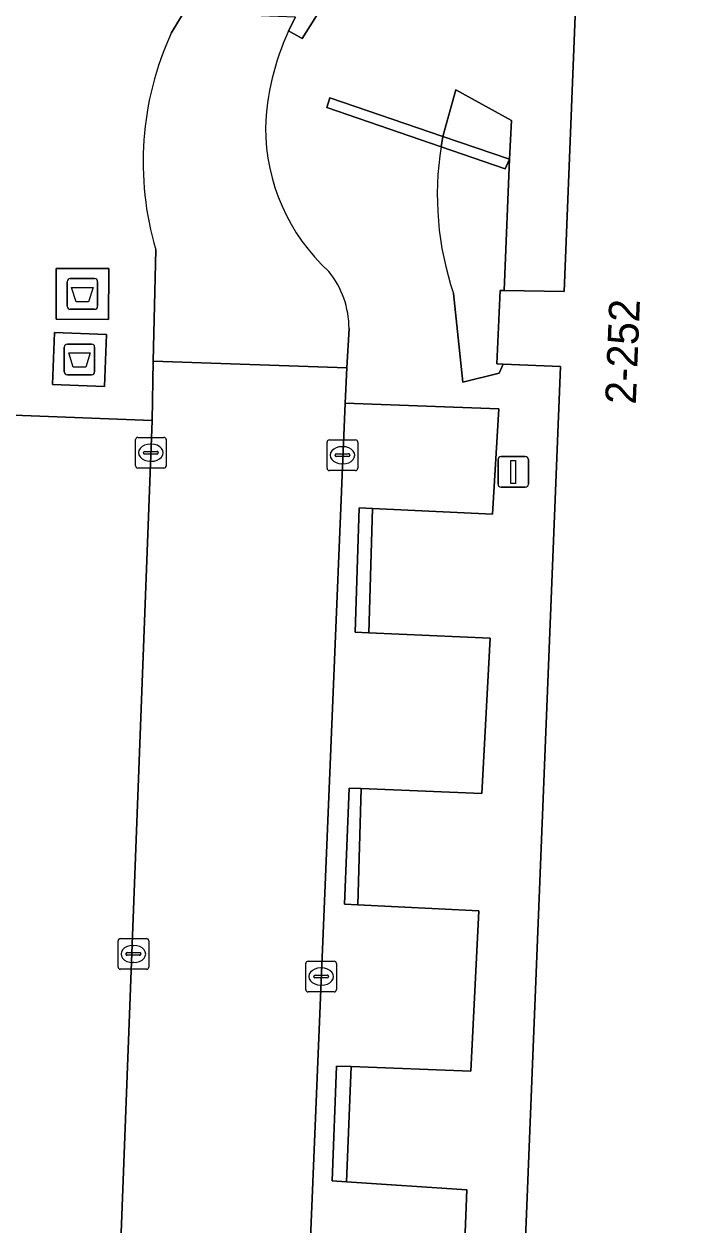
# Model space of a CAD drawing. Extents: x 160077 to 160948, y 386481 to 387498.
# Drawn here: x 160852.52 to 160874.27, y 386651.4 to 386690.54 of the extents above; entities that cross this region are included whole.
import ezdxf

# ---------------------------------------------------------------- set-up
doc = ezdxf.new("R2010")
doc.units = 0
for name, color, linetype in [('IMGEO_Afval_apart_plaats', 7, 'Continuous'), ('IMGEO_Kolk', 7, 'Continuous'), ('IMGEO_Lichtmast', 7, 'Continuous'), ('IMGEO_Muur', 7, 'Continuous'), ('IMGEO_Pand', 7, 'Continuous'), ('IMGEO_Pand_nummerreeks', 7, 'Continuous'), ('IMGEO_Parkeervlak_open', 7, 'Continuous'), ('IMGEO_Rijbaan_lokaal_open', 7, 'Continuous'), ('IMGEO_Voetpad_gesloten', 7, 'Continuous'), ('IMGEO_Voetpad_open', 7, 'Continuous')]:
    doc.layers.add(name, color=color, linetype=linetype)

msp = doc.modelspace()

# ---------------------------------------------------------------- linework, layer by layer
at = {"layer": 'IMGEO_Afval_apart_plaats'}
for p, q in [((160853.93, 386681.341), (160853.93, 386682.141)), ((160853.93, 386682.141), (160853.93, 386681.341)), ((160854.03, 386682.241), (160854.82, 386682.241)), ((160854.82, 386682.241), (160854.03, 386682.241)), ((160854.92, 386682.141), (160854.92, 386681.341)), ((160854.92, 386681.341), (160854.92, 386682.141)), ((160854.82, 386681.241), (160854.03, 386681.241)), ((160854.03, 386681.241), (160854.82, 386681.241)), ((160853.933, 386680.106), (160854.723, 386680.106)), ((160854.723, 386680.106), (160853.933, 386680.106)), ((160853.833, 386679.206), (160853.833, 386680.006)), ((160853.833, 386680.006), (160853.833, 386679.206)), ((160854.823, 386680.006), (160854.823, 386679.206)), ((160854.823, 386679.206), (160854.823, 386680.006)), ((160854.723, 386679.106), (160853.933, 386679.106)), ((160853.933, 386679.106), (160854.723, 386679.106))]:
    msp.add_line(p, q, dxfattribs=at)
for points in [[(160854.073, 386681.955), (160854.777, 386681.955), (160854.628, 386681.485), (160854.222, 386681.485), (160854.073, 386681.955)], [(160853.976, 386679.82), (160854.68, 386679.82), (160854.531, 386679.35), (160854.125, 386679.35), (160853.976, 386679.82)]]:
    msp.add_lwpolyline(points, dxfattribs=at)
for centre, start, end in [((160854.03, 386682.141), 90, 180), ((160854.03, 386682.141), 90, 180), ((160854.82, 386682.141), 0, 90), ((160854.82, 386682.141), 360, 90), ((160854.03, 386681.341), 180, 270), ((160854.03, 386681.341), 180, 270), ((160854.82, 386681.341), 270, 0), ((160854.82, 386681.341), 270, 0), ((160853.933, 386680.006), 90, 180), ((160853.933, 386680.006), 90, 180), ((160854.723, 386680.006), 0, 90), ((160854.723, 386680.006), 360, 90), ((160853.933, 386679.206), 180, 270), ((160853.933, 386679.206), 180, 270), ((160854.723, 386679.206), 270, 0), ((160854.723, 386679.206), 270, 0)]:
    msp.add_arc(centre, 0.1, start, end, dxfattribs=at)
at = {"layer": 'IMGEO_Kolk'}
for p, q in [((160856.155, 386676.141), (160856.155, 386676.993)), ((160856.23, 386677.067), (160857.082, 386677.067)), ((160857.156, 386676.993), (160857.156, 386676.141)), ((160862.477, 386676.984), (160863.329, 386676.984)), ((160856.414, 386676.561), (160856.414, 386676.573)), ((160856.457, 386676.61), (160856.855, 386676.61)), ((160856.643, 386676.847), (160856.668, 386676.847)), ((160856.898, 386676.573), (160856.898, 386676.561)), ((160862.402, 386676.058), (160862.402, 386676.91)), ((160862.89, 386676.764), (160862.915, 386676.764)), ((160863.403, 386676.91), (160863.403, 386676.058)), ((160856.852, 386676.524), (160856.454, 386676.524)), ((160856.666, 386676.287), (160856.641, 386676.287)), ((160862.661, 386676.478), (160862.661, 386676.49)), ((160863.099, 386676.441), (160862.701, 386676.441)), ((160862.704, 386676.527), (160863.102, 386676.527)), ((160862.913, 386676.204), (160862.888, 386676.204)), ((160863.145, 386676.49), (160863.145, 386676.478)), ((160857.082, 386676.067), (160856.23, 386676.067)), ((160863.329, 386675.984), (160862.477, 386675.984)), ((160855.585, 386659.803), (160855.585, 386660.655)), ((160855.66, 386660.729), (160856.512, 386660.729)), ((160856.073, 386660.509), (160856.098, 386660.509)), ((160856.586, 386660.655), (160856.586, 386659.803)), ((160855.844, 386660.223), (160855.844, 386660.235)), ((160856.282, 386660.186), (160855.884, 386660.186)), ((160855.887, 386660.272), (160856.285, 386660.272)), ((160856.328, 386660.235), (160856.328, 386660.223)), ((160856.512, 386659.729), (160855.66, 386659.729)), ((160856.096, 386659.949), (160856.071, 386659.949)), ((160861.707, 386659.067), (160861.707, 386659.919)), ((160861.782, 386659.993), (160862.634, 386659.993)), ((160862.195, 386659.773), (160862.22, 386659.773)), ((160862.708, 386659.919), (160862.708, 386659.067)), ((160861.966, 386659.487), (160861.966, 386659.499)), ((160862.404, 386659.45), (160862.006, 386659.45)), ((160862.009, 386659.536), (160862.407, 386659.536)), ((160862.45, 386659.499), (160862.45, 386659.487)), ((160862.634, 386658.993), (160861.782, 386658.993)), ((160862.218, 386659.213), (160862.193, 386659.213))]:
    msp.add_line(p, q, dxfattribs=at)
for points in [[(160856.155, 386676.141), (160856.155, 386676.993)], [(160856.23, 386677.067), (160857.082, 386677.067)], [(160857.156, 386676.993), (160857.156, 386676.141)], [(160862.477, 386676.984), (160863.329, 386676.984)], [(160862.402, 386676.058), (160862.402, 386676.91)], [(160863.403, 386676.91), (160863.403, 386676.058)], [(160857.082, 386676.067), (160856.23, 386676.067)], [(160863.329, 386675.984), (160862.477, 386675.984)], [(160855.585, 386659.803), (160855.585, 386660.655)], [(160855.66, 386660.729), (160856.512, 386660.729)], [(160856.586, 386660.655), (160856.586, 386659.803)], [(160856.512, 386659.729), (160855.66, 386659.729)], [(160861.707, 386659.067), (160861.707, 386659.919)], [(160861.782, 386659.993), (160862.634, 386659.993)], [(160862.708, 386659.919), (160862.708, 386659.067)], [(160862.634, 386658.993), (160861.782, 386658.993)]]:
    msp.add_lwpolyline(points, dxfattribs=at)
for centre, radius, start, end in [((160856.232, 386676.991), 0.0765, 91.552, 178.448), ((160856.232, 386676.991), 0.0765, 91.552, 178.448), ((160857.08, 386676.991), 0.0765, 1.552, 88.448), ((160857.08, 386676.991), 0.0765, 1.552, 88.448), ((160862.479, 386676.908), 0.0765, 91.552, 178.448), ((160862.479, 386676.908), 0.0765, 91.552, 178.448), ((160863.327, 386676.908), 0.0765, 1.552, 88.448), ((160863.327, 386676.908), 0.0765, 1.552, 88.448), ((160856.454, 386676.57), 0.0403, 85.8775, 175.7526), ((160856.451, 386676.56), 0.0366, 178.938, 274.7102), ((160856.855, 386676.567), 0.043, 264.8664, 352.4533), ((160856.859, 386676.572), 0.0386, 1.7309, 96.639), ((160862.701, 386676.487), 0.0403, 85.8775, 175.7526), ((160862.698, 386676.477), 0.0366, 178.938, 274.7102), ((160863.102, 386676.484), 0.043, 264.8664, 352.4533), ((160863.106, 386676.489), 0.0386, 1.7309, 96.639), ((160856.232, 386676.143), 0.0765, 181.552, 268.448), ((160856.232, 386676.143), 0.0765, 181.552, 268.448), ((160857.08, 386676.143), 0.0765, 271.552, 358.448), ((160857.08, 386676.143), 0.0765, 271.552, 358.448), ((160862.479, 386676.06), 0.0765, 181.552, 268.448), ((160862.479, 386676.06), 0.0765, 181.552, 268.448), ((160863.327, 386676.06), 0.0765, 271.552, 358.448), ((160863.327, 386676.06), 0.0765, 271.552, 358.448), ((160855.662, 386660.653), 0.0765, 91.552, 178.448), ((160855.662, 386660.653), 0.0765, 91.552, 178.448), ((160856.51, 386660.653), 0.0765, 1.552, 88.448), ((160856.51, 386660.653), 0.0765, 1.552, 88.448), ((160855.884, 386660.232), 0.0403, 85.8775, 175.7526), ((160855.881, 386660.222), 0.0366, 178.938, 274.7102), ((160856.285, 386660.229), 0.043, 264.8664, 352.4533), ((160856.289, 386660.234), 0.0386, 1.7309, 96.639), ((160855.662, 386659.805), 0.0765, 181.552, 268.448), ((160855.662, 386659.805), 0.0765, 181.552, 268.448), ((160856.51, 386659.805), 0.0765, 271.552, 358.448), ((160856.51, 386659.805), 0.0765, 271.552, 358.448), ((160861.784, 386659.917), 0.0765, 91.552, 178.448), ((160861.784, 386659.917), 0.0765, 91.552, 178.448), ((160862.632, 386659.917), 0.0765, 1.552, 88.448), ((160862.632, 386659.917), 0.0765, 1.552, 88.448), ((160862.006, 386659.496), 0.0403, 85.8775, 175.7526), ((160862.003, 386659.486), 0.0366, 178.938, 274.7102), ((160862.407, 386659.493), 0.043, 264.8664, 352.4533), ((160862.411, 386659.498), 0.0386, 1.7309, 96.639), ((160861.784, 386659.069), 0.0765, 181.552, 268.448), ((160861.784, 386659.069), 0.0765, 181.552, 268.448), ((160862.632, 386659.069), 0.0765, 271.552, 358.448), ((160862.632, 386659.069), 0.0765, 271.552, 358.448)]:
    msp.add_arc(centre, radius, start, end, dxfattribs=at)
for centre, major_axis, ratio, start_param, end_param in [((160856.642, 386676.567), (-0.387, 0.002), 0.722429, 4.712389, 7.853982), ((160856.667, 386676.567), (-0.39, 0.002), 0.717154, 1.570796, 4.712389), ((160862.889, 386676.484), (-0.387, 0.002), 0.722429, 4.712389, 7.853982), ((160862.914, 386676.484), (-0.39, 0.002), 0.717154, 1.570796, 4.712389), ((160856.072, 386660.229), (-0.387, 0.002), 0.722429, 4.712389, 7.853982), ((160856.097, 386660.229), (-0.39, 0.002), 0.717154, 1.570796, 4.712389), ((160862.194, 386659.493), (-0.387, 0.002), 0.722429, 4.712389, 7.853982), ((160862.219, 386659.493), (-0.39, 0.002), 0.717154, 1.570796, 4.712389)]:
    msp.add_ellipse(centre, major_axis=major_axis, ratio=ratio, start_param=start_param, end_param=end_param, dxfattribs=at)
at = {"layer": 'IMGEO_Lichtmast'}
for p, q in [((160867.976, 386675.542), (160867.976, 386676.342)), ((160867.976, 386676.342), (160867.976, 386675.542)), ((160868.076, 386676.442), (160868.866, 386676.442)), ((160868.866, 386676.442), (160868.076, 386676.442)), ((160868.966, 386676.342), (160868.966, 386675.542)), ((160868.966, 386675.542), (160868.966, 386676.342)), ((160868.866, 386675.442), (160868.076, 386675.442)), ((160868.076, 386675.442), (160868.866, 386675.442))]:
    msp.add_line(p, q, dxfattribs=at)
msp.add_lwpolyline([(160868.396, 386676.317), (160868.546, 386676.317), (160868.546, 386675.567), (160868.396, 386675.567), (160868.396, 386676.317)], dxfattribs=at)
for centre, start, end in [((160868.076, 386676.342), 90, 180), ((160868.076, 386676.342), 90, 180), ((160868.866, 386676.342), 0, 90), ((160868.866, 386676.342), 360, 90), ((160868.076, 386675.542), 180, 270), ((160868.076, 386675.542), 180, 270), ((160868.866, 386675.542), 270, 0), ((160868.866, 386675.542), 270, 0)]:
    msp.add_arc(centre, 0.1, start, end, dxfattribs=at)
at = {"layer": 'IMGEO_Muur'}
for points in [[(160862.491, 386688.137), (160862.395, 386687.817), (160866.121, 386686.539), (160866.18, 386686.874)], [(160868.351, 386686.131), (160866.18, 386686.874), (160866.121, 386686.539), (160868.207, 386685.824)]]:
    msp.add_lwpolyline(points, close=True, dxfattribs=at)
at = {"layer": 'IMGEO_Pand'}
msp.add_lwpolyline([(160871.226, 386709.345), (160870.128, 386681.819), (160868.177, 386681.851), (160868.044, 386681.853), (160867.935, 386679.466), (160868.148, 386679.457), (160870.016, 386679.382), (160867.503, 386616.843), (160869.259, 386616.749), (160870.333, 386616.692), (160870.125, 386610.74), (160871.325, 386610.699), (160871.314, 386610.368), (160872.273, 386610.346), (160872.284, 386610.665), (160873.483, 386610.623), (160873.453, 386609.764), (160877.531, 386609.622)], dxfattribs=at)
at = {"layer": 'IMGEO_Parkeervlak_open'}
for points in [[(160867.351, 386661.635), (160863.408, 386661.828), (160862.968, 386661.85), (160863.119, 386665.635), (160863.517, 386665.619), (160867.445, 386665.462), (160867.715, 386670.521), (160863.767, 386670.699), (160863.314, 386670.719), (160863.449, 386674.772), (160863.883, 386674.751), (160867.792, 386674.566), (160868.002, 386677.995), (160862.99, 386678.181), (160860.19, 386610.649)], [(160866.768, 386647.538), (160866.962, 386652.547), (160863.032, 386652.804), (160862.567, 386652.834), (160862.71, 386656.577), (160863.184, 386656.559), (160867.092, 386656.41), (160867.351, 386661.635)]]:
    msp.add_lwpolyline(points, dxfattribs=at)
msp.add_lwpolyline([(160856.694, 386677.618), (160851.902, 386677.805), (160849.16, 386609.822), (160854.098, 386609.581)], close=True, dxfattribs=at)
at = {"layer": 'IMGEO_Rijbaan_lokaal_open'}
for points in [[(160861.146, 386690.315), (160861.375, 386690.763), (160857.721, 386690.909), (160857.319, 386690.245)], [(160856.813, 386683.184), (160856.735, 386679.548), (160863.05, 386679.33), (160863.117, 386680.613)]]:
    msp.add_lwpolyline(points, dxfattribs=at)
msp.add_lwpolyline([(160860.133, 386609.343), (160860.19, 386610.649), (160862.99, 386678.181), (160863.05, 386679.33), (160856.735, 386679.548), (160856.694, 386677.618), (160854.098, 386609.581)], close=True, dxfattribs=at)
for centre, radius, start, end in [((160866.516, 386686.037), 10.113, 155.4148, 196.3875), ((160868.749, 386686.828), 8.365, 155.3616, 177.7307), ((160866.764, 386687.173), 6.373, 180.1283, 227.5173), ((160860.176, 386680.62), 2.941, 359.8596, 39.0495)]:
    msp.add_arc(centre, radius, start, end, dxfattribs=at)
at = {"layer": 'IMGEO_Voetpad_gesloten'}
for points in [[(160855.281, 386682.568), (160853.571, 386682.571), (160853.568, 386680.914), (160855.278, 386680.911)], [(160855.209, 386680.416), (160853.514, 386680.483), (160853.447, 386678.795), (160855.142, 386678.728)]]:
    msp.add_lwpolyline(points, close=True, dxfattribs=at)
at = {"layer": 'IMGEO_Voetpad_open'}
for points in [[(160866.121, 386686.539), (160862.395, 386687.817), (160862.491, 386688.137), (160866.18, 386686.874), (160866.603, 386688.39), (160868.414, 386687.394), (160868.351, 386686.131), (160868.177, 386681.851), (160870.128, 386681.819), (160871.226, 386709.345)], [(160861.375, 386690.763), (160861.146, 386690.315), (160861.594, 386690.07), (160862.655, 386691.761)], [(160862.655, 386691.761), (160861.594, 386690.07), (160861.146, 386690.315)], [(160857.319, 386690.245), (160857.721, 386690.909)], [(160866.523, 386681.76), (160866.833, 386678.868), (160868.015, 386679.163), (160868.148, 386679.457), (160867.935, 386679.466), (160868.044, 386681.853), (160868.177, 386681.851), (160868.351, 386686.131), (160868.207, 386685.824), (160866.121, 386686.539)], [(160849.632, 386686.066), (160849.305, 386677.9), (160851.902, 386677.805), (160856.694, 386677.618), (160856.735, 386679.548), (160856.813, 386683.184)], [(160868.933, 386610.495), (160869.259, 386616.749), (160867.503, 386616.843), (160870.016, 386679.382), (160868.148, 386679.457), (160868.015, 386679.163), (160866.833, 386678.868), (160866.523, 386681.76)], [(160863.117, 386680.613), (160863.05, 386679.33), (160862.99, 386678.181), (160868.002, 386677.995), (160867.792, 386674.566), (160863.883, 386674.751), (160863.767, 386670.699), (160867.715, 386670.521), (160867.445, 386665.462), (160863.517, 386665.619), (160863.408, 386661.828), (160867.351, 386661.635), (160867.092, 386656.41), (160863.184, 386656.559), (160863.032, 386652.804), (160866.962, 386652.547), (160866.768, 386647.538)]]:
    msp.add_lwpolyline(points, dxfattribs=at)
for points in [[(160868.351, 386686.131), (160868.414, 386687.394), (160866.603, 386688.39), (160866.18, 386686.874)], [(160855.281, 386682.568), (160855.278, 386680.911), (160853.568, 386680.914), (160853.571, 386682.571)], [(160855.209, 386680.416), (160855.142, 386678.728), (160853.447, 386678.795), (160853.514, 386680.483)], [(160863.883, 386674.751), (160863.449, 386674.772), (160863.314, 386670.719), (160863.767, 386670.699)], [(160863.517, 386665.619), (160863.119, 386665.635), (160862.968, 386661.85), (160863.408, 386661.828)], [(160863.184, 386656.559), (160862.71, 386656.577), (160862.567, 386652.834), (160863.032, 386652.804)]]:
    msp.add_lwpolyline(points, close=True, dxfattribs=at)
for centre, radius, start, end in [((160866.516, 386686.037), 10.113, 155.4148, 196.3875), ((160868.749, 386686.828), 8.365, 155.3616, 177.7307), ((160866.764, 386687.173), 6.373, 180.1283, 227.5173), ((160875.953, 386684.96), 9.958, 170.8744, 198.7422), ((160875.953, 386684.96), 9.958, 170.8744, 198.7422), ((160860.176, 386680.62), 2.941, 359.8596, 39.0495)]:
    msp.add_arc(centre, radius, start, end, dxfattribs=at)

# ---------------------------------------------------------------- texts
at = {"layer": 'IMGEO_Pand_nummerreeks'}
msp.add_text('2-252', height=1, rotation=87.6969, dxfattribs=at).set_placement((160872.468, 386678.132))

doc.saveas('drawing.dxf')
